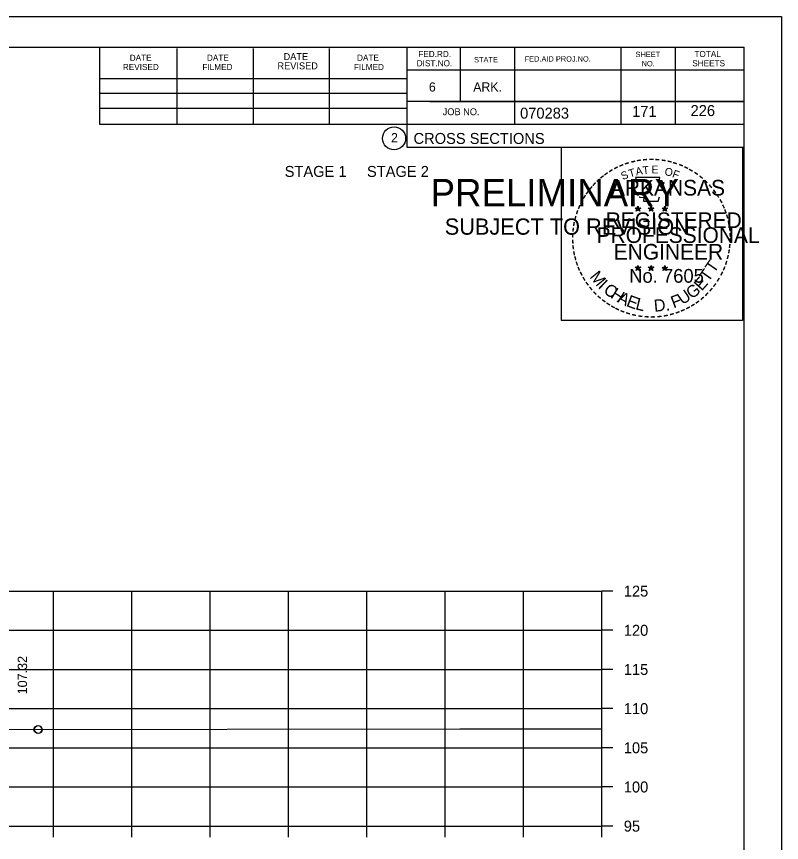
# Model space of a CAD drawing. Extents: x 1175611 to 1176402, y -433344 to -416213.
# Drawn here: x 1175846.2 to 1175943.9, y -428115.5 to -428010.1 of the extents above; entities that cross this region are included whole.
import ezdxf

# ---------------------------------------------------------------- set-up
doc = ezdxf.new("R2010")
doc.units = 0
for name, color, linetype in [('Default', 7, 'Continuous'), ('R_Axis', 7, 'Continuous'), ('R_Axis Annot', 7, 'Continuous'), ('R_Border', 7, 'Continuous'), ('R_Border Notes', 7, 'Continuous'), ('R_Border PE', 7, 'Continuous'), ('R_Border Prem', 7, 'Continuous'), ('R_Exist Surface', 7, 'Continuous'), ('R_Grid', 7, 'Continuous'), ('R_No Plot', 7, 'Continuous'), ('R_Xsect Elev', 7, 'Continuous')]:
    doc.layers.add(name, color=color, linetype=linetype)

msp = doc.modelspace()

# ---------------------------------------------------------------- linework, layer by layer
at = {"layer": 'R_Axis'}
for p, q in [((1175920.97, -428113.44), (1175920.97, -428083.44)), ((1175922.37, -428083.44), (1175920.97, -428083.44)), ((1175922.37, -428088.44), (1175920.97, -428088.44)), ((1175922.37, -428093.44), (1175920.97, -428093.44)), ((1175922.37, -428098.44), (1175920.97, -428098.44)), ((1175922.37, -428103.44), (1175920.97, -428103.44)), ((1175922.37, -428108.44), (1175920.97, -428108.44)), ((1175640.97, -428113.44), (1175920.97, -428113.44)), ((1175850.97, -428114.84), (1175850.97, -428113.44)), ((1175860.97, -428114.84), (1175860.97, -428113.44)), ((1175870.97, -428114.84), (1175870.97, -428113.44)), ((1175880.97, -428114.84), (1175880.97, -428113.44)), ((1175890.97, -428114.84), (1175890.97, -428113.44)), ((1175900.97, -428114.84), (1175900.97, -428113.44)), ((1175910.97, -428114.84), (1175910.97, -428113.44)), ((1175920.97, -428114.84), (1175920.97, -428113.44)), ((1175922.37, -428113.44), (1175920.97, -428113.44))]:
    msp.add_line(p, q, dxfattribs=at)
at = {"layer": 'R_Border'}
for p, q in [((1175622.97, -428013.98), (1175939.15, -428013.98)), ((1175856.89, -428023.86), (1175856.89, -428013.98)), ((1175866.75, -428023.86), (1175866.75, -428014.18)), ((1175876.51, -428023.86), (1175876.51, -428014.18)), ((1175886.19, -428023.86), (1175886.19, -428014.18)), ((1175896.05, -428013.98), (1175896.05, -428026.78)), ((1175902.89, -428013.98), (1175902.89, -428020.92)), ((1175909.83, -428013.98), (1175909.83, -428023.86)), ((1175923.41, -428013.98), (1175923.41, -428023.86)), ((1175930.35, -428013.98), (1175930.35, -428023.86)), ((1175939.15, -428219.44), (1175939.15, -428013.98)), ((1175939.15, -428016.92), (1175896.05, -428016.92)), ((1175939.15, -428016.9), (1175939.15, -428016.9)), ((1175856.89, -428018), (1175896.05, -428018)), ((1175856.89, -428019.86), (1175896.05, -428019.86)), ((1175939.15, -428020.92), (1175896.05, -428020.92)), ((1175899.01, -428020.92), (1175939.15, -428020.92)), ((1175856.89, -428023.86), (1175856.89, -428021.8)), ((1175856.89, -428021.8), (1175896.05, -428021.8)), ((1175939.15, -428023.86), (1175856.89, -428023.86)), ((1175896.05, -428026.78), (1175939.15, -428026.78))]:
    msp.add_line(p, q, dxfattribs=at)
msp.add_circle((1175894.44, -428025.64), 1.47, dxfattribs=at)
at = {"layer": 'R_Border PE'}
for p, q in [((1175925.23, -428034.53), (1175925.58, -428034.64)), ((1175925.23, -428034.53), (1175925.49, -428034.58)), ((1175925.23, -428034.53), (1175925.47, -428034.65)), ((1175925.37, -428034.94), (1175925.58, -428034.64)), ((1175925.37, -428034.94), (1175925.49, -428034.7)), ((1175925.37, -428034.94), (1175925.58, -428034.72)), ((1175925.58, -428034.28), (1175925.54, -428034.53)), ((1175925.58, -428034.64), (1175925.58, -428034.28)), ((1175925.58, -428034.28), (1175925.63, -428034.53)), ((1175925.93, -428034.53), (1175925.58, -428034.64)), ((1175925.8, -428034.94), (1175925.58, -428034.64)), ((1175925.8, -428034.94), (1175925.58, -428034.73)), ((1175925.93, -428034.53), (1175925.64, -428034.58)), ((1175925.8, -428034.94), (1175925.66, -428034.65)), ((1175925.93, -428034.53), (1175925.73, -428034.63)), ((1175926.9, -428034.53), (1175927.25, -428034.64)), ((1175926.9, -428034.53), (1175927.16, -428034.58)), ((1175926.9, -428034.53), (1175927.14, -428034.65)), ((1175927.04, -428034.94), (1175927.25, -428034.64)), ((1175927.04, -428034.94), (1175927.16, -428034.7)), ((1175927.04, -428034.94), (1175927.25, -428034.72)), ((1175927.25, -428034.28), (1175927.21, -428034.53)), ((1175927.25, -428034.64), (1175927.25, -428034.28)), ((1175927.25, -428034.28), (1175927.3, -428034.53)), ((1175927.6, -428034.53), (1175927.25, -428034.64)), ((1175927.47, -428034.94), (1175927.25, -428034.64)), ((1175927.47, -428034.94), (1175927.25, -428034.73)), ((1175927.6, -428034.53), (1175927.31, -428034.58)), ((1175927.47, -428034.94), (1175927.33, -428034.65)), ((1175927.6, -428034.53), (1175927.4, -428034.63)), ((1175928.67, -428034.54), (1175929.02, -428034.65)), ((1175928.67, -428034.54), (1175928.92, -428034.59)), ((1175928.67, -428034.54), (1175928.91, -428034.67)), ((1175928.8, -428034.95), (1175929.02, -428034.65)), ((1175928.8, -428034.95), (1175928.93, -428034.71)), ((1175928.8, -428034.95), (1175929.02, -428034.73)), ((1175929.02, -428034.29), (1175928.98, -428034.54)), ((1175929.02, -428034.65), (1175929.02, -428034.29)), ((1175929.02, -428034.29), (1175929.07, -428034.54)), ((1175929.36, -428034.54), (1175929.02, -428034.65)), ((1175929.23, -428034.95), (1175929.02, -428034.65)), ((1175929.23, -428034.95), (1175929.02, -428034.74)), ((1175929.36, -428034.54), (1175929.08, -428034.59)), ((1175929.23, -428034.95), (1175929.09, -428034.66)), ((1175929.36, -428034.54), (1175929.16, -428034.65)), ((1175925.23, -428042.1), (1175925.58, -428042.22)), ((1175925.23, -428042.1), (1175925.48, -428042.15)), ((1175925.23, -428042.1), (1175925.47, -428042.23)), ((1175925.36, -428042.51), (1175925.58, -428042.22)), ((1175925.36, -428042.51), (1175925.49, -428042.27)), ((1175925.36, -428042.51), (1175925.58, -428042.3)), ((1175925.58, -428041.85), (1175925.54, -428042.1)), ((1175925.58, -428042.22), (1175925.58, -428041.85)), ((1175925.58, -428041.85), (1175925.63, -428042.1)), ((1175925.93, -428042.1), (1175925.58, -428042.22)), ((1175925.79, -428042.51), (1175925.58, -428042.22)), ((1175925.79, -428042.51), (1175925.58, -428042.3)), ((1175925.93, -428042.1), (1175925.64, -428042.15)), ((1175925.79, -428042.51), (1175925.66, -428042.22)), ((1175925.93, -428042.1), (1175925.72, -428042.21)), ((1175926.9, -428042.1), (1175927.25, -428042.22)), ((1175926.9, -428042.1), (1175927.15, -428042.15)), ((1175926.9, -428042.1), (1175927.14, -428042.23)), ((1175927.03, -428042.51), (1175927.25, -428042.22)), ((1175927.03, -428042.51), (1175927.16, -428042.27)), ((1175927.03, -428042.51), (1175927.25, -428042.3)), ((1175927.25, -428041.85), (1175927.21, -428042.1)), ((1175927.25, -428042.22), (1175927.25, -428041.85)), ((1175927.25, -428041.85), (1175927.3, -428042.1)), ((1175927.6, -428042.1), (1175927.25, -428042.22)), ((1175927.46, -428042.51), (1175927.25, -428042.22)), ((1175927.46, -428042.51), (1175927.25, -428042.3)), ((1175927.6, -428042.1), (1175927.31, -428042.15)), ((1175927.46, -428042.51), (1175927.32, -428042.22)), ((1175927.6, -428042.1), (1175927.39, -428042.21)), ((1175928.67, -428042.11), (1175929.02, -428042.23)), ((1175928.67, -428042.11), (1175928.92, -428042.16)), ((1175928.67, -428042.11), (1175928.9, -428042.24)), ((1175928.8, -428042.52), (1175929.02, -428042.23)), ((1175928.8, -428042.52), (1175928.93, -428042.28)), ((1175928.8, -428042.52), (1175929.01, -428042.31)), ((1175929.02, -428041.86), (1175928.97, -428042.11)), ((1175929.23, -428042.52), (1175929.01, -428042.31)), ((1175929.02, -428042.23), (1175929.02, -428041.86)), ((1175929.02, -428041.86), (1175929.06, -428042.11)), ((1175929.36, -428042.11), (1175929.02, -428042.23)), ((1175929.23, -428042.52), (1175929.02, -428042.23)), ((1175929.36, -428042.11), (1175929.08, -428042.16)), ((1175929.23, -428042.52), (1175929.09, -428042.23)), ((1175929.36, -428042.11), (1175929.16, -428042.22))]:
    msp.add_line(p, q, dxfattribs=at)
for points in [[(1175925.28, -428030.65), (1175925.54, -428031.48)], [(1175928.79, -428031.58), (1175928.93, -428031.29), (1175928.24, -428031.32), (1175928.39, -428030.65), (1175925.28, -428030.65)], [(1175925.77, -428033.08), (1175925.77, -428033.16), (1175926.33, -428033.18), (1175926.28, -428033.66), (1175928.15, -428033.66), (1175928.35, -428033.12)], [(1175925.58, -428034.28), (1175925.8, -428034.94), (1175925.23, -428034.53), (1175925.93, -428034.53), (1175925.37, -428034.94), (1175925.58, -428034.28)], [(1175927.25, -428034.28), (1175927.47, -428034.94), (1175926.9, -428034.53), (1175927.6, -428034.53), (1175927.04, -428034.94), (1175927.25, -428034.28)], [(1175929.02, -428034.29), (1175929.23, -428034.95), (1175928.67, -428034.54), (1175929.36, -428034.54), (1175928.8, -428034.95), (1175929.02, -428034.29)], [(1175925.58, -428041.85), (1175925.79, -428042.51), (1175925.23, -428042.1), (1175925.93, -428042.1), (1175925.36, -428042.51), (1175925.58, -428041.85)], [(1175927.25, -428041.85), (1175927.46, -428042.51), (1175926.9, -428042.1), (1175927.6, -428042.1), (1175927.03, -428042.51), (1175927.25, -428041.85)], [(1175929.02, -428041.86), (1175929.23, -428042.52), (1175928.67, -428042.11), (1175929.36, -428042.11), (1175928.8, -428042.52), (1175929.02, -428041.86)]]:
    msp.add_lwpolyline(points, dxfattribs=at)
for centre, radius in [((1175925.58, -428034.64), 0.172), ((1175925.58, -428034.64), 0.145), ((1175925.58, -428034.64), 0.116), ((1175925.58, -428034.64), 0.0991), ((1175925.58, -428034.64), 0.0747), ((1175925.58, -428034.64), 0.0495), ((1175925.58, -428034.64), 0.0296), ((1175927.25, -428034.64), 0.172), ((1175927.25, -428034.64), 0.145), ((1175927.25, -428034.64), 0.116), ((1175927.25, -428034.64), 0.0991), ((1175927.25, -428034.64), 0.0747), ((1175927.25, -428034.64), 0.0495), ((1175927.25, -428034.64), 0.0296), ((1175929.02, -428034.66), 0.172), ((1175929.02, -428034.66), 0.145), ((1175929.02, -428034.66), 0.116), ((1175929.02, -428034.66), 0.0991), ((1175929.02, -428034.66), 0.0747), ((1175929.02, -428034.66), 0.0495), ((1175929.02, -428034.66), 0.0296), ((1175925.58, -428042.22), 0.172), ((1175925.58, -428042.22), 0.145), ((1175925.58, -428042.22), 0.116), ((1175925.58, -428042.22), 0.0991), ((1175925.58, -428042.22), 0.0747), ((1175925.58, -428042.22), 0.0495), ((1175925.58, -428042.22), 0.0296), ((1175927.25, -428042.22), 0.172), ((1175927.25, -428042.22), 0.145), ((1175927.25, -428042.22), 0.116), ((1175927.25, -428042.22), 0.0991), ((1175927.25, -428042.22), 0.0747), ((1175927.25, -428042.22), 0.0495), ((1175927.25, -428042.22), 0.0296), ((1175929.01, -428042.23), 0.172), ((1175929.01, -428042.23), 0.145), ((1175929.01, -428042.23), 0.116), ((1175929.01, -428042.23), 0.0991), ((1175929.01, -428042.23), 0.0747), ((1175929.01, -428042.23), 0.0495), ((1175929.01, -428042.23), 0.0296)]:
    msp.add_circle(centre, radius, dxfattribs=at)
at = {"layer": 'R_Exist Surface'}
msp.add_lwpolyline([(1175843.32, -428101.12), (1175902.82, -428101.03), (1175920.97, -428101.02)], dxfattribs=at)
at = {"layer": 'R_Grid'}
for p, q in [((1175640.97, -428083.44), (1175920.97, -428083.44)), ((1175850.97, -428113.44), (1175850.97, -428083.44)), ((1175860.97, -428113.44), (1175860.97, -428083.44)), ((1175870.97, -428113.44), (1175870.97, -428083.44)), ((1175880.97, -428113.44), (1175880.97, -428083.44)), ((1175890.97, -428113.44), (1175890.97, -428083.44)), ((1175900.97, -428113.44), (1175900.97, -428083.44)), ((1175910.97, -428113.44), (1175910.97, -428083.44)), ((1175920.97, -428113.44), (1175920.97, -428083.44)), ((1175640.97, -428088.44), (1175920.97, -428088.44)), ((1175640.97, -428093.44), (1175920.97, -428093.44)), ((1175640.97, -428098.44), (1175920.97, -428098.44)), ((1175640.97, -428103.44), (1175920.97, -428103.44)), ((1175640.97, -428108.44), (1175920.97, -428108.44)), ((1175640.97, -428113.44), (1175920.97, -428113.44))]:
    msp.add_line(p, q, dxfattribs=at)
at = {"layer": 'R_No Plot'}
msp.add_line((1175610.57, -428010.08), (1175943.91, -428010.08), dxfattribs=at)
for points in [[(1175610.57, -428010.08), (1175943.91, -428010.08), (1175943.91, -428223.42), (1175610.57, -428223.42)], [(1175915.82, -428026.75), (1175938.92, -428026.75), (1175938.92, -428048.9), (1175915.82, -428048.9)]]:
    msp.add_lwpolyline(points, close=True, dxfattribs=at)
for centre in [(1175848.96, -428101.11), (1175849.02, -428101.11)]:
    msp.add_circle(centre, 0.5, dxfattribs=at)

# ---------------------------------------------------------------- texts
at = {"layer": 'Default'}
msp.add_text('STAGE 1     STAGE 2', height=1.4, dxfattribs=at).set_placement((1175880.47, -428030.56))
at = {"layer": 'R_Axis Annot'}
for s, p in [('125', (1175923.77, -428084.14)), ('120', (1175923.77, -428089.14)), ('115', (1175923.77, -428094.14)), ('110', (1175923.77, -428099.14)), ('105', (1175923.77, -428104.14)), ('100', (1175923.77, -428109.14)), ('95', (1175923.77, -428114.14))]:
    msp.add_text(s, height=1.4, dxfattribs=at).set_placement(p)
at = {"layer": 'R_Border'}
for s, height, p in [('DATE', 0.782, (1175860.69, -428015.74)), ('DATE', 0.782, (1175870.55, -428015.74)), ('DATE', 0.879, (1175880.33, -428015.64)), ('DATE', 0.782, (1175889.71, -428015.74)), ('FED.RD.', 0.782, (1175897.53, -428015.26)), ('SHEET', 0.684, (1175925.27, -428015.26)), ('TOTAL', 0.782, (1175932.79, -428015.26)), ('REVISED', 0.879, (1175879.55, -428016.82)), ('DIST.NO.', 0.782, (1175897.33, -428016.44)), ('STATE', 0.684, (1175904.65, -428015.94)), ('FED.AID PROJ.NO.', 0.684, (1175911.11, -428015.84)), ('NO.', 0.684, (1175926.05, -428016.44)), ('SHEETS', 0.782, (1175932.51, -428016.44)), ('REVISED', 0.782, (1175859.81, -428016.92)), ('FILMED', 0.782, (1175869.97, -428016.92)), ('FILMED', 0.782, (1175889.31, -428016.92)), ('6', 1.17, (1175898.89, -428019.66)), ('ARK.', 1.172, (1175904.55, -428019.66)), ('JOB NO.', 0.879, (1175900.65, -428022.68)), ('070283', 1.4, (1175910.53, -428023.12)), ('2', 1.17, (1175894.06, -428026.13)), ('CROSS SECTIONS', 1.4, (1175896.92, -428026.35))]:
    msp.add_text(s, height=height, rotation=360, dxfattribs=at).set_placement(p)
at = {"layer": 'R_Border Notes'}
for s, p in [('171', (1175924.83, -428022.9)), ('226', (1175932.3, -428022.79))]:
    msp.add_text(s, height=1.4, dxfattribs=at).set_placement(p)
at = {"layer": 'R_Border PE'}
for s, height, rotation, p in [('-', 1.6, 19.1761, (1175924.02, -428029.53)), ('-', 1.6, 13.6301, (1175924.77, -428029.29)), ('-', 1.6, 10.2193, (1175925.45, -428029.12)), ('-', 1.6, 5.8968, (1175926.18, -428029.01)), ('-', 1.6, 0.1862, (1175926.95, -428028.94)), ('-', 1.6, 357.743, (1175927.67, -428028.95)), ('-', 1.6, 352.1617, (1175928.42, -428029.01)), ('-', 1.6, 347.2049, (1175929.14, -428029.12)), ('-', 1.6, 342.3362, (1175929.77, -428029.28)), ('-', 1.6, 34.0636, (1175922.16, -428030.48)), ('-', 1.6, 28.7918, (1175922.76, -428030.11)), ('-', 1.6, 24.3072, (1175923.39, -428029.8)), ('T', 1, 16.4036, (1175924.54, -428030.64)), ('A', 1, 11.2132, (1175925.37, -428030.39)), ('T', 1, 6.0228, (1175926.22, -428030.23)), ('E', 1, 0.8323, (1175927.32, -428030.12)), ('O', 1, 350.4515, (1175928.93, -428030.33)), ('F', 1, 340.0707, (1175929.88, -428030.56)), ('-', 1.6, 337.8551, (1175930.51, -428029.5)), ('-', 1.6, 334.1211, (1175931.14, -428029.77)), ('-', 1.6, 329.6409, (1175931.72, -428030.06)), ('-', 1.6, 42.9622, (1175920.67, -428031.67)), ('-', 1.6, 38.9507, (1175921.1, -428031.26)), ('-', 1.6, 36.2317, (1175921.58, -428030.88)), ('S', 1, 21.594, (1175923.63, -428030.98)), ('-', 1.6, 325.8627, (1175932.36, -428030.42)), ('-', 1.6, 320.5297, (1175932.97, -428030.84)), ('-', 1.6, 50.6142, (1175919.82, -428032.64)), ('-', 1.6, 48.423, (1175920.22, -428032.15)), ('ARKANSAS', 2, 360, (1175922.13, -428032.94)), ('-', 1.6, 315.5786, (1175933.57, -428031.33)), ('-', 1.6, 309.8797, (1175934.14, -428031.88)), ('-', 1.6, 58.0706, (1175919.08, -428033.73)), ('-', 1.6, 54.2325, (1175919.41, -428033.2)), ('-', 1.6, 306.6522, (1175934.66, -428032.48)), ('-', 1.4, 303.6753, (1175935.15, -428033.05)), ('-', 1.6, 62.8713, (1175918.77, -428034.34)), ('-', 1.6, 299.6684, (1175935.47, -428033.66)), ('-', 1.6, 72.3945, (1175918.29, -428035.59)), ('-', 1.6, 67.7743, (1175918.51, -428034.96)), ('DWB', 0.01, 360, (1175925.57, -428034.65)), ('DWB', 0.01, 360, (1175927.24, -428034.65)), ('DWB', 0.01, 360, (1175929, -428034.66)), ('-', 1.6, 294.6628, (1175935.79, -428034.27)), ('-', 1.6, 290.5728, (1175936.05, -428034.85)), ('-', 1.6, 75.461, (1175918.09, -428036.3)), ('REGISTERED', 2, 360, (1175921.45, -428037.09)), ('-', 1.6, 285.1233, (1175936.28, -428035.43)), ('-', 1.6, 85.1863, (1175917.89, -428037.7)), ('-', 1.6, 81.2013, (1175917.96, -428037.01)), ('PROFESSIONAL', 2, 360, (1175920.3, -428038.99)), ('-', 1.6, 280.5493, (1175936.48, -428036.17)), ('-', 1.6, 276.5962, (1175936.65, -428036.94)), ('-', 1.6, 89.0622, (1175917.86, -428038.4)), ('-', 1.6, 274.3301, (1175936.71, -428037.66)), ('-', 1.6, 94.1959, (1175917.9, -428039.13)), ('ENGINEER', 2, 360, (1175922.49, -428041.12)), ('-', 1.6, 263.5172, (1175936.72, -428038.96)), ('-', 1.6, 269.9407, (1175936.74, -428038.29)), ('-', 1.6, 98.9479, (1175917.97, -428039.8)), ('-', 1.6, 101.7149, (1175918.1, -428040.53)), ('-', 1.6, 260.9953, (1175936.65, -428039.61)), ('-', 1.6, 105.4578, (1175918.27, -428041.12)), ('-', 1.6, 109.0874, (1175918.48, -428041.76)), ('T', 1.54, 55.055, (1175935.3, -428042.95)), ('-', 1.6, 252.8681, (1175936.36, -428041.01)), ('-', 1.6, 255.7626, (1175936.54, -428040.29)), ('-', 1.6, 114.0643, (1175918.73, -428042.35)), ('No. 7605', 1.757, 360, (1175924.46, -428044.07)), ('DWB', 0.01, 360, (1175925.56, -428042.22)), ('DWB', 0.01, 360, (1175927.23, -428042.22)), ('DWB', 0.01, 360, (1175929, -428042.23)), ('T', 1.54, 55.055, (1175934.57, -428044.07)), ('-', 1.6, 247.8887, (1175936.14, -428041.68)), ('-', 1.6, 115.7289, (1175919.04, -428042.97)), ('-', 1.6, 120.4471, (1175919.4, -428043.56)), ('M', 1.54, 308.9175, (1175919.35, -428043.33)), ('E', 1.54, 48.7313, (1175933.72, -428045.2)), ('-', 1.6, 239.0712, (1175935.48, -428043.06)), ('-', 1.6, 244.6197, (1175935.87, -428042.31)), ('-', 1.6, 125.8934, (1175919.8, -428044.12)), ('I', 1.54, 316.4636, (1175920.39, -428044.65)), ('C', 1.54, 324.0197, (1175921.06, -428045.27)), ('G', 1.54, 38.2173, (1175932.47, -428046.22)), ('-', 1.6, 233.8452, (1175935.08, -428043.72)), ('-', 1.6, 130.7181, (1175920.26, -428044.67)), ('-', 1.6, 134.2238, (1175920.78, -428045.21)), ('H', 1.54, 327.5342, (1175921.97, -428045.92)), ('A', 1.54, 332.5513, (1175922.83, -428046.46)), ('F', 1.54, 20.8202, (1175930.13, -428047.35)), ('U', 1.54, 34.4052, (1175931.27, -428046.95)), ('-', 1.6, 225.7653, (1175934.17, -428044.85)), ('-', 1.6, 231.2538, (1175934.65, -428044.28)), ('-', 1.6, 138.9338, (1175921.3, -428045.68)), ('-', 1.6, 144.6463, (1175921.86, -428046.08)), ('-', 1.6, 148.0898, (1175922.42, -428046.45)), ('E', 1.54, 339.2068, (1175923.99, -428047.02)), ('L', 1.54, 346.2929, (1175925.18, -428047.45)), ('D.', 1.54, 5.2602, (1175927.68, -428047.78)), ('-', 1.6, 215.7363, (1175933.1, -428045.83)), ('-', 1.6, 221.0851, (1175933.65, -428045.36)), ('-', 1.6, 151.5704, (1175923, -428046.78)), ('-', 1.6, 154.6002, (1175923.52, -428047.03)), ('-', 1.6, 158.5612, (1175924.15, -428047.28)), ('-', 1.6, 204.2516, (1175931.38, -428046.88)), ('-', 1.6, 207.3568, (1175932.01, -428046.56)), ('-', 1.6, 212.2491, (1175932.56, -428046.21)), ('-', 1.6, 162.7983, (1175924.83, -428047.49)), ('-', 1.6, 167.5555, (1175925.55, -428047.66)), ('-', 1.6, 173.1155, (1175926.32, -428047.77)), ('-', 1.6, 176.5183, (1175927.07, -428047.82)), ('-', 1.6, 181.5918, (1175927.81, -428047.8)), ('-', 1.6, 185.8167, (1175928.62, -428047.73)), ('-', 1.6, 191.2858, (1175929.36, -428047.59)), ('-', 1.6, 195.4743, (1175930.09, -428047.39)), ('-', 1.6, 200.7184, (1175930.76, -428047.15))]:
    msp.add_text(s, height=height, rotation=rotation, dxfattribs=at).set_placement(p)
at = {"layer": 'R_Border Prem'}
for s, height, p in [('PRELIMINARY', 3.5, (1175899.1, -428034.32)), ('DWB', 0.01, (1175899.85, -428032.47)), ('SUBJECT TO REVISION', 2.0751, (1175900.91, -428037.94))]:
    msp.add_text(s, height=height, rotation=360, dxfattribs=at).set_placement(p)
at = {"layer": 'R_Xsect Elev'}
msp.add_text('107.32', height=1.2, rotation=90, dxfattribs=at).set_placement((1175847.58, -428096.62))

doc.saveas('drawing.dxf')
